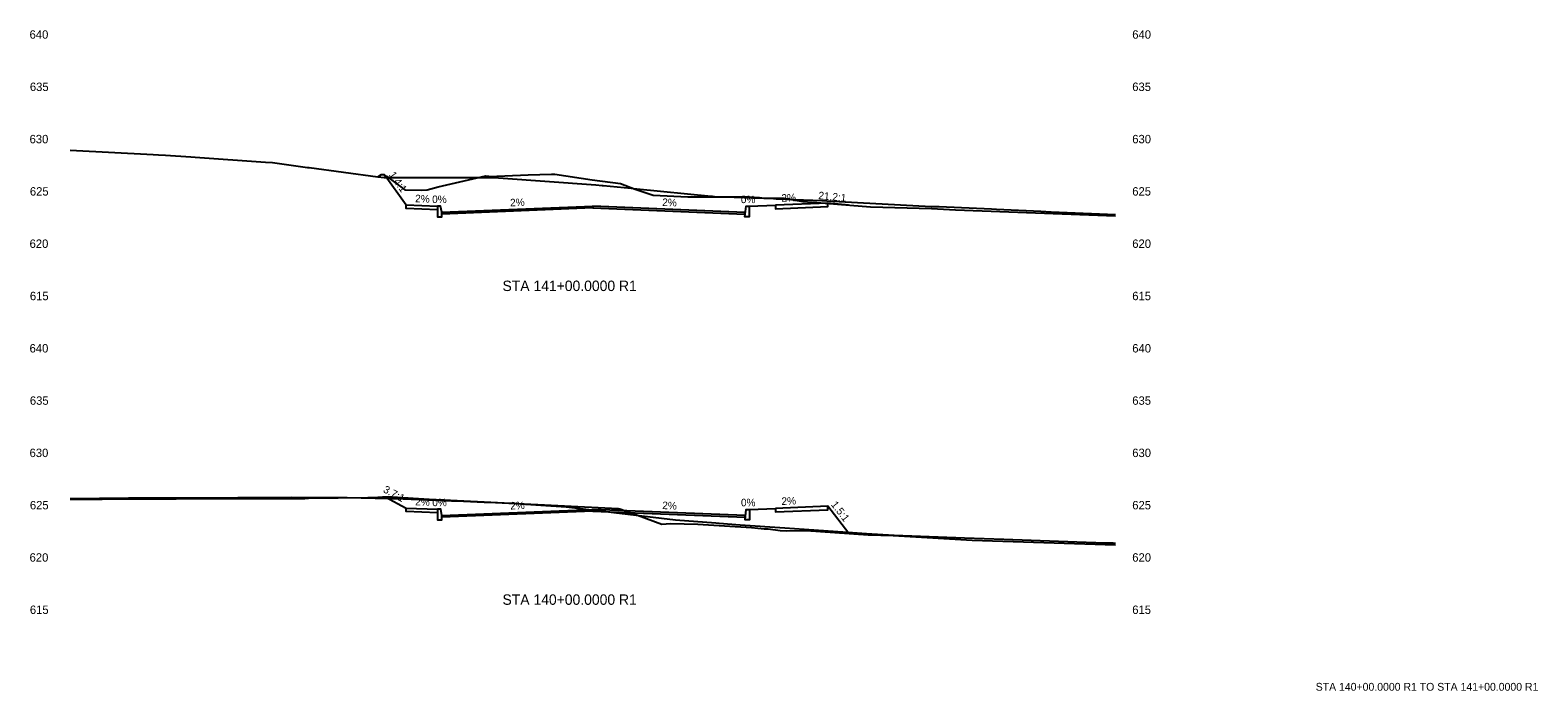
# Model space of a CAD drawing. Extents: x 12 to 301, y 16 to 1707.
# Drawn here: x 12.4 to 300.8, y 465.9 to 592.2 of the extents above; entities that cross this region are included whole.
import ezdxf

# ---------------------------------------------------------------- set-up
doc = ezdxf.new("R2010")
doc.units = 0
for name, color, linetype in [('BORD_text_large_2', 7, 'Continuous'), ('Default', 7, 'Continuous'), ('Draft_XS_Point_Label_Indicator', 7, 'Continuous'), ('Draft_XS_Text', 7, 'Continuous'), ('Grade_Veg_Grass', 7, 'Continuous'), ('P_XS_Sections', 7, 'Continuous'), ('Road_Curb', 7, 'Continuous'), ('Road_Pave_Asphalt', 7, 'Continuous'), ('Road_Sidewalk', 7, 'Continuous'), ('Terrain_Exterior', 7, 'Continuous')]:
    doc.layers.add(name, color=color, linetype=linetype)

msp = doc.modelspace()

# ---------------------------------------------------------------- linework, layer by layer
at = {"layer": 'Default'}
for points in [[(20, 569.26), (35.91, 568.44), (36.94, 568.4), (38.25, 568.33), (43.1, 568), (43.95, 567.94), (57.39, 567.02), (58.71, 566.9), (59.18, 566.85), (65.44, 566), (65.73, 565.96), (78.86, 564.17), (79.61, 564.65), (79.88, 564.62), (79.88, 564.62), (79.88, 564.62), (79.88, 564.62), (79.89, 564.61), (80.11, 564.65), (80.22, 564.44), (80.53, 564.33), (81.81, 563.39), (84.07, 561.67), (87.15, 561.65), (88.32, 561.7), (90.4, 562.27), (99.57, 564.37), (100.11, 564.29), (100.21, 564.28), (107.65, 564.54), (112.09, 564.72), (112.29, 564.7), (112.57, 564.69), (112.77, 564.68), (119.88, 563.62), (125.29, 562.91), (125.34, 562.9), (128.15, 561.82), (131.58, 560.68), (138.22, 560.36), (147.85, 560.38), (149.89, 560.35), (151.88, 560.22), (152.82, 560.13), (155.52, 560.11), (156.58, 560.12), (160.19, 559.44), (162.85, 559.25), (173.12, 558.47), (184.82, 558.16), (189.4, 557.89), (220, 556.73)], [(20, 502.54), (24.28, 502.55), (25.17, 502.55), (26.18, 502.55), (40.31, 502.61), (54.64, 502.67), (55.33, 502.67), (56.12, 502.66), (64.92, 502.7), (65.62, 502.72), (76.98, 502.87), (77.3, 502.88), (77.45, 502.89), (77.89, 502.9), (78.92, 502.94), (79.77, 502.97), (80.35, 502.99), (80.85, 503.01), (81.14, 502.99), (81.61, 502.98), (88.73, 502.58), (90.04, 502.51), (91.51, 502.43), (124.87, 500.75), (124.98, 500.71), (125.17, 500.68), (128.56, 499.51), (133.2, 497.74), (134.88, 497.88), (140.12, 497.79), (145.2, 497.45), (150.39, 497.13), (152.8, 496.9), (153.58, 496.85), (155.88, 496.59), (157.11, 496.52), (160.81, 496.55), (163.56, 496.38), (172.69, 495.74), (177.49, 495.6), (192.62, 494.69), (220, 493.81)]]:
    msp.add_lwpolyline(points, dxfattribs=at)
at = {"layer": 'Grade_Veg_Grass'}
for points in [[(80.29, 564.42), (80.29, 564.42), (84.29, 558.81)], [(149.96, 558.56), (154.96, 558.76)], [(168.96, 558.78), (164.96, 559.16), (164.96, 559.16)], [(80.31, 502.99), (84.31, 500.85), (84.31, 500.85)], [(149.98, 500.59), (154.98, 500.79)], [(168.98, 496), (168.98, 496), (164.98, 501.19)]]:
    msp.add_lwpolyline(points, dxfattribs=at)
at = {"layer": 'Road_Curb'}
for points in [[(90.29, 558.57), (90.29, 556.57), (91.12, 556.57), (91.12, 557.4), (90.89, 558.57), (90.29, 558.57)], [(149.96, 558.56), (149.96, 556.56), (149.12, 556.56), (149.35, 558.56), (149.96, 558.56)], [(90.31, 500.61), (90.31, 498.61), (91.15, 498.61), (91.15, 499.44), (90.92, 500.61), (90.31, 500.61)], [(149.98, 500.59), (149.98, 498.59), (149.15, 498.59), (149.38, 500.59), (149.98, 500.59)]]:
    msp.add_lwpolyline(points, dxfattribs=at)
at = {"layer": 'Road_Pave_Asphalt'}
for points in [[(91.12, 557.4), (120, 558.56), (120, 558.23), (120, 558.23), (91.12, 557.07), (91.12, 557.07), (91.12, 557.07), (91.12, 557.4), (91.12, 557.4)], [(120, 558.56), (120, 558.56), (120, 558.23), (120, 558.23), (120, 558.23), (149.12, 557.06), (149.12, 557.06), (149.12, 557.39), (120, 558.56)], [(91.15, 499.44), (120, 500.59), (120, 500.26), (120, 500.26), (91.15, 499.11), (91.15, 499.11), (91.15, 499.11), (91.15, 499.44), (91.15, 499.44)], [(149.15, 499.43), (120, 500.59), (120, 500.26), (120, 500.26), (149.15, 499.09), (149.15, 499.09), (149.15, 499.09), (149.15, 499.43), (149.15, 499.43)]]:
    msp.add_lwpolyline(points, dxfattribs=at)
at = {"layer": 'Road_Sidewalk'}
for points in [[(90.29, 558.57), (90.29, 557.9), (84.29, 558.14), (84.29, 558.81), (90.29, 558.57)], [(154.96, 558.76), (154.96, 558.09), (164.96, 558.49), (164.96, 559.16), (154.96, 558.76)], [(90.31, 500.61), (90.31, 499.94), (84.31, 500.18), (84.31, 500.85), (90.31, 500.61)], [(154.98, 500.79), (154.98, 500.13), (164.98, 500.53), (164.98, 501.19), (154.98, 500.79)]]:
    msp.add_lwpolyline(points, dxfattribs=at)
at = {"layer": 'Terrain_Exterior'}
for points in [[(20, 569.26), (35.91, 568.44), (36.94, 568.4), (38.25, 568.33), (43.1, 568), (43.95, 567.94), (57.39, 567.02), (58.71, 566.9), (59.18, 566.85), (65.44, 566), (65.73, 565.96), (78.86, 564.17), (80.12, 564.05), (94.68, 564.06), (100.34, 564.07), (101.05, 564.07), (101.96, 564), (120.59, 562.63), (121.82, 562.54), (121.91, 562.53), (121.98, 562.52), (127.33, 562), (127.35, 562), (128.43, 561.89), (142.63, 560.5), (142.92, 560.47), (143.29, 560.45), (154.57, 560.02), (155.08, 560), (163.85, 559.66), (164.26, 559.64), (164.77, 559.6), (184.78, 558.54), (186.25, 558.49), (196.3, 558.04), (197.25, 558), (205.72, 557.62), (206.7, 557.57), (207.72, 557.52), (220, 556.99)], [(20, 502.69), (31.16, 502.79), (40.81, 502.83), (52.09, 502.86), (62.28, 502.92), (73.03, 502.86), (83.76, 502.61), (92.98, 502.26), (93.96, 502.22), (99.21, 502), (100.13, 501.96), (105.24, 501.75), (114.89, 501.07), (122.48, 500.18), (124.03, 500), (126.71, 499.69), (135.83, 498.6), (143.57, 498), (144.18, 497.95), (148.19, 497.64), (156.76, 497.07), (169.67, 496.15), (172.36, 496), (176.56, 495.76), (177.69, 495.69), (191.14, 495.18), (198.63, 494.93), (212.62, 494.4), (218.05, 494.22), (219.56, 494.17), (220, 494.16)]]:
    msp.add_lwpolyline(points, dxfattribs=at)

# ---------------------------------------------------------------- texts
at = {"layer": 'BORD_text_large_2'}
msp.add_text('STA 140+00.0000 R1 TO STA 141+00.0000 R1', height=1.5, dxfattribs=at).set_placement((258.32, 465.92))
at = {"layer": 'Draft_XS_Point_Label_Indicator'}
for p in [(80.28, 564.41), (84.28, 558.8), (90.28, 558.56), (90.88, 558.56), (91.11, 557.39), (119.99, 558.55), (119.99, 558.55), (149.11, 557.38), (149.34, 558.55), (149.94, 558.55), (154.94, 558.75), (164.94, 559.15), (168.94, 558.77), (80.3, 502.97), (84.3, 500.83), (90.3, 500.59), (90.91, 500.59), (91.14, 499.43), (119.99, 500.58), (119.99, 500.58), (149.14, 499.42), (149.37, 500.58), (149.97, 500.58), (154.97, 500.78), (164.97, 501.18), (168.97, 495.99)]:
    msp.add_text('X', height=0.024, dxfattribs=at).set_placement(p)
at = {"layer": 'Draft_XS_Text'}
for s, height, p in [('640', 1.608, (12.26, 590.6)), ('640', 1.608, (223.22, 590.6)), ('635', 1.608, (12.32, 580.6)), ('635', 1.608, (223.22, 580.6)), ('630', 1.608, (12.26, 570.6)), ('630', 1.608, (223.22, 570.6)), ('625', 1.608, (12.32, 560.6)), ('0%', 1.44, (89.28, 559.17)), ('0%', 1.44, (89.28, 559.17)), ('0%', 1.44, (89.28, 559.17)), ('0%', 1.44, (148.34, 559.16)), ('0%', 1.44, (148.34, 559.16)), ('0%', 1.44, (148.34, 559.16)), ('625', 1.608, (223.22, 560.6)), ('620', 1.608, (12.26, 550.6)), ('620', 1.608, (223.22, 550.6)), ('STA 141+00.0000 R1', 1.992, (102.74, 542.35)), ('615', 1.608, (12.32, 540.6)), ('615', 1.608, (223.22, 540.6)), ('640', 1.608, (12.26, 530.6)), ('640', 1.608, (223.22, 530.6)), ('635', 1.608, (12.32, 520.6)), ('635', 1.608, (223.22, 520.6)), ('630', 1.608, (12.26, 510.6)), ('630', 1.608, (223.22, 510.6)), ('625', 1.608, (12.32, 500.6)), ('0%', 1.44, (148.36, 501.19)), ('0%', 1.44, (148.36, 501.19)), ('0%', 1.44, (148.36, 501.19)), ('625', 1.608, (223.22, 500.6)), ('620', 1.608, (12.26, 490.6)), ('620', 1.608, (223.22, 490.6)), ('615', 1.608, (12.32, 480.6)), ('STA 140+00.0000 R1', 1.992, (102.74, 482.35)), ('615', 1.608, (223.22, 480.6))]:
    msp.add_text(s, height=height, dxfattribs=at).set_placement(p)
for s, rotation, p in [('1.4:1', 305.5084, (80.92, 564.57)), ('1.4:1', 305.5084, (80.92, 564.57)), ('1.4:1', 305.5084, (80.92, 564.57)), ('2%', 357.7094, (86, 559.34)), ('2%', 357.7094, (86, 559.34)), ('2%', 357.7094, (86, 559.34)), ('2%', 2.2906, (104.22, 558.53)), ('2%', 2.2906, (104.22, 558.53)), ('2%', 2.2906, (104.22, 558.53)), ('2%', 357.7094, (133.27, 558.63)), ('2%', 357.7094, (133.27, 558.63)), ('2%', 357.7094, (133.27, 558.63)), ('2%', 2.2906, (156.12, 559.41)), ('2%', 2.2906, (156.12, 559.41)), ('2%', 2.2906, (156.12, 559.41)), ('21.2:1', 354.6204, (163.12, 559.94)), ('21.2:1', 354.6204, (163.12, 559.94)), ('21.2:1', 354.6204, (163.12, 559.94)), ('3.7:1', 331.8463, (79.78, 503.96)), ('3.7:1', 331.8463, (79.78, 503.96)), ('3.7:1', 331.8463, (79.78, 503.96)), ('2%', 357.7094, (86.02, 501.38)), ('2%', 357.7094, (86.02, 501.38)), ('2%', 357.7094, (86.02, 501.38)), ('0%', 0, (89.3, 501.21)), ('0%', 0, (89.3, 501.21)), ('0%', 0, (89.3, 501.21)), ('2%', 2.2906, (104.24, 500.56)), ('2%', 2.2906, (104.24, 500.56)), ('2%', 2.2906, (104.24, 500.56)), ('2%', 357.7094, (133.28, 500.66)), ('2%', 357.7094, (133.28, 500.66)), ('2%', 357.7094, (133.28, 500.66)), ('2%', 2.2906, (156.14, 501.44)), ('2%', 2.2906, (156.14, 501.44)), ('2%', 2.2906, (156.14, 501.44)), ('1.5:1', 307.6099, (165.5, 501.5)), ('1.5:1', 307.6099, (165.5, 501.5)), ('1.5:1', 307.6099, (165.5, 501.5))]:
    msp.add_text(s, height=1.44, rotation=rotation, dxfattribs=at).set_placement(p)
at = {"layer": 'P_XS_Sections'}
for p in [(20, 540), (20, 480)]:
    msp.add_text('-', height=0.0001, dxfattribs=at).set_placement(p)

doc.saveas('drawing.dxf')
